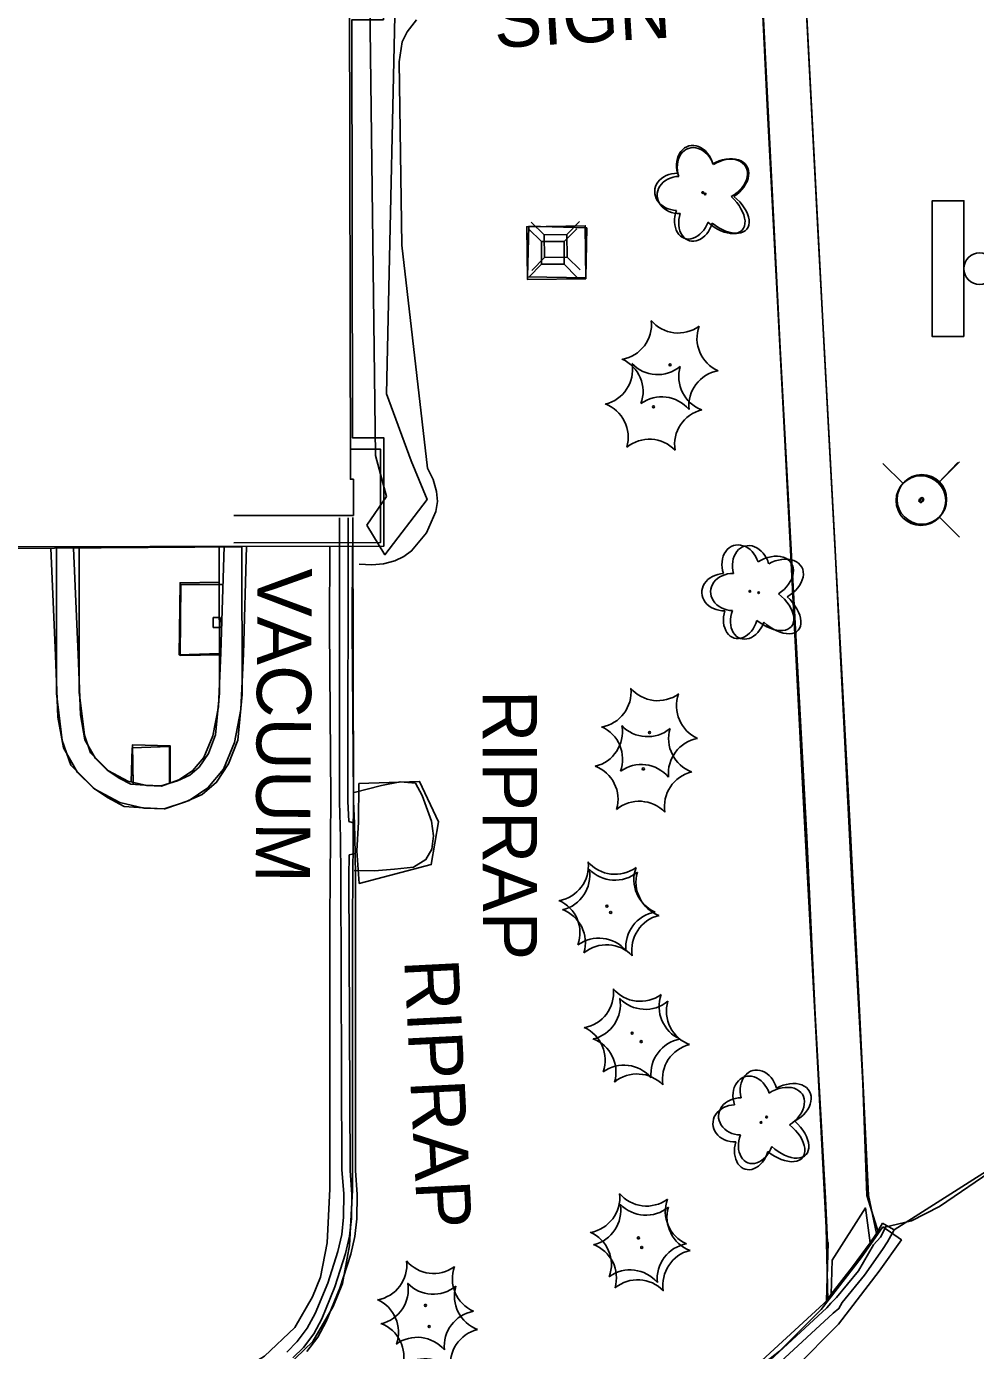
# Model space of a CAD drawing. Extents: x 588843 to 2552415, y 180129 to 269402.
# Drawn here: x 594584.3 to 594689.3, y 184634.7 to 184781.1 of the extents above; entities that cross this region are included whole.
import ezdxf

# ---------------------------------------------------------------- set-up
doc = ezdxf.new("R2010")
doc.units = 0
for name, color, linetype in [('Default', 7, 'Continuous'), ('E_AREA', 7, 'Continuous'), ('E_BLD', 7, 'Continuous'), ('E_BLD_HvyDash', 7, 'Continuous'), ('E_BLD_Text', 7, 'Continuous'), ('E_BLD_Vacuum', 7, 'Continuous'), ('E_DRN_RipRap', 7, 'Continuous'), ('E_DRN_RipRap_Text', 7, 'Continuous'), ('E_DWY', 7, 'Continuous'), ('E_LAND_ShrubLine', 7, 'Continuous'), ('E_LAND_Vegetation', 7, 'Continuous'), ('E_MISCPROP_Planter', 7, 'Continuous'), ('E_PATH_Sidewalk', 7, 'Continuous'), ('E_RDWY_AsphConc', 7, 'Continuous'), ('E_RDWY_C_and_G', 7, 'Continuous'), ('E_SGN', 7, 'Continuous'), ('E_SGN_Text', 7, 'Continuous'), ('E_UTL_AG_Bold', 7, 'Continuous'), ('E_UTL_WHydrant', 7, 'Continuous')]:
    doc.layers.add(name, color=color, linetype=linetype)

# ---------------------------------------------------------------- blocks, each defined once
blk = doc.blocks.new('HYD')
at = {"layer": 'Default'}
for p, q in [((-3.84, 3.84), (-8.32, 8.32)), ((3.84, 3.84), (8.32, 8.32))]:
    blk.add_line(p, q, dxfattribs=at)
for radius in [5.48, 0.42]:
    blk.add_circle((0, 0), radius, dxfattribs=at)
blk = doc.blocks.new('RIPRT')
at = {"layer": 'E_DRN_RipRap_Text'}
blk.add_text('RIPRAP', height=12, dxfattribs=at).set_placement((-0.14, -3.59))
blk = doc.blocks.new('PED')
at = {"layer": 'Default'}
for p, q in [((-2.5, 2.5), (-5.33, 5.33)), ((2.5, 2.5), (5.33, 5.33)), ((-2.5, -2.5), (-5.33, -5.33)), ((2.5, -2.5), (5.33, -5.33))]:
    blk.add_line(p, q, dxfattribs=at)
blk.add_lwpolyline([(-2.5, -2.5), (2.5, -2.5), (2.5, 2.5), (-2.5, 2.5)], close=True, dxfattribs=at)
blk = doc.blocks.new('VACO')
at = {"layer": 'E_BLD_Vacuum'}
blk.add_lwpolyline([(0, 1.5), (0, 0), (2.2, 0), (2.2, 1.5), (0, 1.5)], close=True, dxfattribs=at)
blk = doc.blocks.new('VAC')
at = {"layer": 'E_BLD_Text'}
blk.add_text('VACUUM', height=12, dxfattribs=at).set_placement((-33.33, -6))
blk = doc.blocks.new('CTRE_1_1')
at = {"layer": 'Default'}
blk.add_circle((0, 0), 0.223, dxfattribs=at)
for centre, start, end in [((-11.97, 8.96), 280.2067, 5.9716), ((1.81, 14.92), 220.2113, 305.9762), ((13.83, 5.89), 160.2113, 245.9762), ((-13.83, -5.9), 340.2113, 65.9762), ((12.03, -9.04), 100.2511, 185.9272), ((-1.81, -14.93), 40.2113, 125.9762)]:
    blk.add_arc(centre, 7.87, start, end, dxfattribs=at)
blk = doc.blocks.new('DTRE_1_1')
at = {"layer": 'Default'}
blk.add_circle((-0.18, 0), 0.183, dxfattribs=at)
for centre, major_axis, ratio in [((-1.87, 5.32), (1.36, -4.98), 0.782863), ((4.06, 2.74), (-5.27, -2.93), 0.691916), ((-5.87, 0.15), (4.93, -0.12), 0.832022), ((3.54, -3.71), (-5.01, 4.58), 0.560249), ((-2.49, -5.24), (1.8, 4.86), 0.716896)]:
    blk.add_ellipse(centre, major_axis=major_axis, ratio=ratio, start_param=1.570796, end_param=4.712389, dxfattribs=at)
blk = doc.blocks.new('SGN_1')
at = {"layer": 'Default'}
blk.add_lwpolyline([(-3.5, -15), (-10.5, -15), (-10.5, 15), (-3.5, 15)], close=True, dxfattribs=at)
blk.add_circle((0, 0), 3.5, dxfattribs=at)
blk = doc.blocks.new('PED_3')
at = {"layer": 'E_UTL_AG_Bold'}
for p, q in [((-8.2, 8.2), (-17.48, 17.48)), ((8.2, 8.2), (17.48, 17.48)), ((-8.2, -8.2), (-17.48, -17.48)), ((8.2, -8.2), (17.48, -17.48))]:
    blk.add_line(p, q, dxfattribs=at)
blk.add_lwpolyline([(-8.2, -8.2), (8.2, -8.2), (8.2, 8.2), (-8.2, 8.2)], close=True, dxfattribs=at)
blk = doc.blocks.new('HYD_3')
at = {"layer": 'E_UTL_WHydrant'}
for p, q in [((-12.59, 12.59), (-27.29, 27.29)), ((12.6, 12.59), (27.29, 27.29))]:
    blk.add_line(p, q, dxfattribs=at)
for radius in [18, 1.38]:
    blk.add_circle((0, 0), radius, dxfattribs=at)
blk = doc.blocks.new('RIPRT_3')
at = {"layer": 'E_DRN_RipRap_Text'}
blk.add_text('RIPRAP', height=39.37, dxfattribs=at).set_placement((-0.46, -11.78))
blk = doc.blocks.new('DTRE_4')
at = {"layer": 'E_LAND_Vegetation'}
blk.add_circle((-0.6, 0), 0.601, dxfattribs=at)
for centre, major_axis, ratio in [((-6.14, 17.45), (4.46, -16.34), 0.782863), ((13.31, 8.98), (-17.3, -9.61), 0.691916), ((-19.26, 0.5), (16.18, -0.4), 0.832022), ((11.62, -12.16), (-16.44, 15.03), 0.560249), ((-8.18, -17.2), (5.91, 15.93), 0.716896)]:
    blk.add_ellipse(centre, major_axis=major_axis, ratio=ratio, start_param=1.570796, end_param=4.712389, dxfattribs=at)
blk = doc.blocks.new('CTRE_4')
at = {"layer": 'E_LAND_Vegetation'}
blk.add_circle((0, 0), 0.733, dxfattribs=at)
for centre, radius, start, end in [((-39.28, 29.41), 25.81, 280.2067, 5.97162), ((5.93, 48.96), 25.81, 220.21132, 305.97623), ((45.37, 19.34), 25.81, 160.21133, 245.97624), ((-45.37, -19.35), 25.81, 340.21132, 65.97623), ((39.47, -29.65), 25.83, 100.25111, 185.92721), ((-5.93, -48.97), 25.81, 40.21133, 125.97624)]:
    blk.add_arc(centre, radius, start, end, dxfattribs=at)
blk = doc.blocks.new('SIGN_3')
at = {"layer": 'E_SGN'}
blk.add_text('SIGN', height=39.37, dxfattribs=at).set_placement((-56.13, -19.68))

msp = doc.modelspace()

# ---------------------------------------------------------------- linework, layer by layer
at = {"layer": 'E_AREA'}
msp.add_lwpolyline([(594646.19, 184753.21), (594639.73, 184753.12), (594639.65, 184758.97), (594646.11, 184759.07)], close=True, dxfattribs=at)
for points in [[(594605.67, 184711.8), (594601.23, 184711.63), (594601.33, 184719.62), (594605.65, 184719.67)], [(594596.13, 184697.33), (594596.06, 184701.69), (594600.24, 184701.58), (594600.24, 184697.47)]]:
    msp.add_lwpolyline(points, dxfattribs=at)
at = {"layer": 'E_BLD'}
for points in [[(594608.14, 184723.58), (594571.85, 184723.33), (594571.78, 184734.03), (594574.21, 184734.05), (594573.89, 184781.74), (594571.61, 184781.72), (594571.54, 184792.23), (594601.99, 184792.44)], [(594597.01, 184789.06), (594620.38, 184789.1), (594620.39, 184785.1), (594620.06, 184785.1), (594620.15, 184731.06), (594620.48, 184731.06), (594620.49, 184727.06), (594607.25, 184727.04)], [(594620.15, 184734.36), (594623.48, 184734.37), (594623.49, 184724.07), (594607.25, 184724.04)]]:
    msp.add_lwpolyline(points, dxfattribs=at)
msp.add_lwpolyline([(594571.85, 184792.25), (594623.79, 184792.33), (594623.8, 184781.84), (594620.3, 184781.83), (594620.37, 184735.63), (594623.84, 184735.63), (594623.86, 184723.66), (594572.06, 184723.57), (594572.05, 184734.14), (594575.19, 184734.15), (594575.11, 184783.48), (594571.86, 184783.48)], close=True, dxfattribs=at)
at = {"layer": 'E_BLD_HvyDash'}
msp.add_lwpolyline([(594673.3, 184640.99), (594673.42, 184644.74), (594677.08, 184650.51), (594677.62, 184646.65)], dxfattribs=at)
at = {"layer": 'E_DRN_RipRap'}
for points in [[(594621.1, 184697.43), (594627.8, 184697.66), (594629.89, 184693.2), (594629.09, 184688.46), (594621.12, 184686.37), (594620.87, 184689.99), (594621.04, 184693.16)], [(594620.58, 184696.41), (594623.57, 184697.19), (594625.64, 184697.62), (594627.33, 184697.45), (594628.07, 184696.11), (594629.1, 184693.26), (594629.35, 184691.65), (594629.14, 184690.17), (594628.5, 184689.02), (594627.14, 184688.19), (594625.03, 184687.97), (594622.82, 184687.78), (594620.58, 184687.81)], [(594621.1, 184697.43), (594621.04, 184693.16)]]:
    msp.add_lwpolyline(points, dxfattribs=at)
at = {"layer": 'E_DWY'}
for points in [[(594587.02, 184723.43), (594587.56, 184711.58), (594587.81, 184704.74), (594588.42, 184701.38), (594589.97, 184698.64), (594591.71, 184696.94), (594593.31, 184695.88), (594595.16, 184694.89), (594597.29, 184694.74), (594599.58, 184694.64), (594601.93, 184695.39), (594603.75, 184696.2), (594605.35, 184697.56), (594606.68, 184699.6), (594607.71, 184702.2), (594608.19, 184707.27), (594608.14, 184723.58)], [(594587.67, 184723.6), (594587.66, 184707.38), (594588.29, 184702.18), (594589.24, 184699.46), (594591.89, 184696.78), (594594.65, 184695.33), (594597.31, 184694.7), (594599.65, 184694.62), (594602.32, 184695.56), (594604.4, 184696.93), (594606.12, 184698.99), (594607.35, 184701.96), (594608.05, 184705.59), (594608.33, 184711.75), (594608.68, 184723.63)], [(594589.53, 184723.45), (594590.06, 184711.68), (594590.3, 184705.01), (594590.8, 184702.24), (594591.97, 184700.18), (594593.28, 184698.9), (594594.59, 184698.03), (594595.87, 184697.35), (594597.43, 184697.24), (594599.25, 184697.16), (594601.03, 184697.72), (594602.4, 184698.34), (594603.45, 184699.23), (594604.45, 184700.75), (594605.25, 184702.79), (594605.69, 184707.39), (594605.64, 184723.56)], [(594590.17, 184723.6), (594590.16, 184707.53), (594590.74, 184702.75), (594591.41, 184700.82), (594593.4, 184698.82), (594595.53, 184697.69), (594597.64, 184697.19), (594599.27, 184697.14), (594601.2, 184697.81), (594602.71, 184698.81), (594603.96, 184700.3), (594604.95, 184702.68), (594605.56, 184705.88), (594605.83, 184711.85), (594606.18, 184723.63)], [(594617.87, 184652.26), (594617.87, 184682.51), (594617.98, 184695.78), (594617.85, 184714.65), (594617.87, 184723.65)], [(594620.37, 184652.26), (594620.37, 184682.5), (594620.48, 184695.78), (594620.35, 184714.65), (594620.37, 184723.65)], [(594698.83, 184659.48), (594691.63, 184655), (594685.27, 184650.67), (594682.16, 184649.1), (594679.09, 184648.35)], [(594554.3, 184628.4), (594573.37, 184627.04), (594585.2, 184627.24), (594601.3, 184628.05), (594604.86, 184628.68), (594608.73, 184630.03), (594612.19, 184632.11), (594615.99, 184635.73), (594618.23, 184639.6), (594619.27, 184642.16), (594620.05, 184646.34), (594620.38, 184652.49)], [(594554.48, 184630.89), (594573.44, 184629.54), (594585.12, 184629.74), (594601.03, 184630.54), (594604.23, 184631.1), (594607.66, 184632.3), (594610.67, 184634.11), (594614.01, 184637.29), (594615.97, 184640.7), (594616.86, 184642.87), (594617.57, 184646.64), (594617.88, 184652.63)], [(594679.01, 184648.41), (594676.6, 184645.01), (594672.2, 184639.3), (594667.6, 184634.68), (594662.06, 184630.33), (594656.62, 184627.07), (594652.4, 184625.21), (594646.92, 184622.88), (594643.5, 184622.02), (594637.03, 184621.21)], [(594679.01, 184648.41), (594681.05, 184646.97), (594678.61, 184643.52), (594674.09, 184637.65), (594669.27, 184632.81), (594663.48, 184628.26), (594657.77, 184624.85), (594653.4, 184622.91), (594647.72, 184620.51), (594643.97, 184619.56), (594637.34, 184618.73)]]:
    msp.add_lwpolyline(points, dxfattribs=at)
at = {"layer": 'E_LAND_ShrubLine'}
for points in [[(594622.17, 184792.64), (594625.27, 184792.33), (594624.15, 184740.49), (594626.86, 184733.08), (594628.62, 184728.8), (594623.96, 184722.7), (594621.98, 184725.96)], [(594622.17, 184792.64), (594622.92, 184733.69), (594624.14, 184729.13), (594621.98, 184725.96)]]:
    msp.add_lwpolyline(points, dxfattribs=at)
at = {"layer": 'E_MISCPROP_Planter'}
msp.add_lwpolyline([(594627.46, 184781.83), (594626.43, 184780.52), (594626.43, 184780.52), (594625.89, 184779.4), (594625.89, 184779.4), (594625.53, 184777.18), (594625.53, 184777.18), (594625.83, 184756.91), (594628.68, 184732.26), (594629.29, 184731.02), (594629.67, 184729.69), (594629.67, 184729.69), (594629.76, 184728.58), (594629.59, 184727.49), (594629.59, 184727.49), (594628.57, 184725.14), (594628.57, 184725.14), (594626.91, 184723.15), (594626.91, 184723.15), (594626.04, 184722.51), (594625.07, 184722.05), (594625.07, 184722.05), (594623.82, 184721.71), (594622.53, 184721.58), (594622.53, 184721.58), (594621.11, 184721.68)], dxfattribs=at)
at = {"layer": 'E_PATH_Sidewalk'}
for points in [[(594669.6, 184841.07), (594668.31, 184833.93), (594668.28, 184832.41), (594669.05, 184813.25), (594670.72, 184811.95), (594673.71, 184809.15), (594675.9, 184805.35), (594677.5, 184799.87), (594677.72, 184794.89), (594677.23, 184792.47), (594675.59, 184789.26), (594673.55, 184786.77), (594671.36, 184784.84), (594670.49, 184783.96), (594671.86, 184757.97), (594673.7, 184723.96), (594675.62, 184685.94), (594676.8, 184664.3), (594677.24, 184651.89), (594678.54, 184647.75)], [(594672.94, 184640.26), (594672.75, 184648.36), (594671.86, 184665.3), (594670.32, 184693.9), (594668.16, 184735.38), (594666.26, 184771.65), (594665.57, 184786.08), (594670.81, 184791.14), (594672.55, 184794.02), (594672.81, 184796.71), (594672.11, 184801.41), (594670.94, 184804.1), (594668.6, 184807.03), (594665.88, 184809.34), (594664.37, 184810.49), (594663.32, 184831.88), (594660.05, 184831.9), (594659.4, 184836.03)], [(594672.76, 184640.23), (594672.95, 184646.7), (594672.9, 184646.72), (594672.67, 184651.6), (594671.54, 184671.85), (594670.6, 184691.48), (594667.67, 184745.54), (594665.59, 184786.32)], [(594678.3, 184647.67), (594677.43, 184651.88), (594676.42, 184672.34), (594675.42, 184691.86), (594672.55, 184744.93), (594670.49, 184784.28)], [(594606.06, 184719.41), (594601.39, 184719.42), (594601.34, 184711.56), (594605.82, 184711.64)], [(594600.14, 184697.44), (594600.15, 184701.5), (594596.01, 184701.36), (594595.91, 184697.6)]]:
    msp.add_lwpolyline(points, dxfattribs=at)
at = {"layer": 'E_RDWY_AsphConc'}
msp.add_lwpolyline([(594639.88, 184759.03), (594639.72, 184753.44), (594646.18, 184753.3), (594646.28, 184758.83)], close=True, dxfattribs=at)
msp.add_lwpolyline([(594680.24, 184648.09), (594698.74, 184659.86)], dxfattribs=at)
at = {"layer": 'E_RDWY_C_and_G'}
for points in [[(594618.95, 184726.8), (594618.96, 184695.38), (594619.04, 184691.41), (594619.1, 184686.98), (594619.2, 184654.72), (594619.41, 184652.11), (594619.4, 184649.49), (594619.4, 184649.49), (594619.19, 184647.57), (594618.77, 184645.68), (594618.77, 184645.68), (594617.64, 184642.21), (594616.26, 184638.83), (594616.26, 184638.83), (594615.38, 184637.21), (594614.28, 184635.73), (594614.28, 184635.73), (594613.12, 184634.56)], [(594620.42, 184726.82), (594620.48, 184695.44), (594620.61, 184693.04), (594620.63, 184691.36), (594620.66, 184689.68), (594620.7, 184687.04), (594620.73, 184654.66), (594620.91, 184651.98), (594620.86, 184649.3), (594620.86, 184649.3), (594620.64, 184647.34), (594620.21, 184645.41), (594620.21, 184645.41), (594618.99, 184641.64), (594617.48, 184637.96), (594617.48, 184637.96), (594616.54, 184636.23), (594615.34, 184634.65)], [(594619.91, 184726.79), (594619.88, 184695.46), (594619.98, 184693.23), (594620.61, 184693.04)], [(594620.66, 184689.68), (594620.02, 184689.53), (594619.98, 184687.12), (594620.13, 184654.65), (594620.31, 184652), (594620.27, 184649.35), (594620.27, 184649.35), (594620.05, 184647.39), (594619.62, 184645.46), (594619.62, 184645.46), (594618.44, 184641.8), (594616.99, 184638.24), (594616.99, 184638.24), (594616.1, 184636.59), (594614.97, 184635.09), (594614.97, 184635.09), (594613.8, 184633.93)], [(594627.93, 184620.38), (594642.38, 184622.21), (594646.24, 184623.13), (594646.24, 184623.13), (594649.73, 184624.28), (594649.73, 184624.28), (594652.52, 184625.46), (594663.8, 184631.94), (594672.48, 184639.95), (594672.76, 184640.23), (594673.3, 184640.99), (594675.67, 184643.99), (594677.62, 184646.65), (594678.3, 184647.67), (594678.95, 184648.83)], [(594628.07, 184619.86), (594642.43, 184621.64), (594646.35, 184622.42), (594646.35, 184622.42), (594649.9, 184623.82), (594649.9, 184623.82), (594651.31, 184624.41), (594652.74, 184624.98), (594664.15, 184631.48), (594672.8, 184639.45), (594673.27, 184640), (594673.87, 184640.61), (594676.31, 184643.55), (594677.97, 184646.43), (594678.73, 184647.29), (594679.41, 184648.56)], [(594628.14, 184618.94), (594642.49, 184620.72), (594646.72, 184621.65), (594646.72, 184621.65), (594650.51, 184622.53), (594650.51, 184622.53), (594653.34, 184623.69), (594664.79, 184630.8), (594673.52, 184638.86), (594674.15, 184639.39), (594674.52, 184640.04), (594676.96, 184643.06), (594678.97, 184645.93), (594679.51, 184646.77), (594680.24, 184648.09), (594679.41, 184648.56), (594678.95, 184648.83)]]:
    msp.add_lwpolyline(points, dxfattribs=at)

# ---------------------------------------------------------------- block references
at = {"layer": 'E_BLD_Text', "xscale": 0.5000000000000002, "yscale": 0.5000000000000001, "rotation": -90.36283032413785}
msp.add_blockref('VAC', (594612.79, 184704.55), dxfattribs=at)
at = {"layer": 'E_BLD_Vacuum', "xscale": 0.5000000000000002, "yscale": 0.5000000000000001, "rotation": -90.36283032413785}
msp.add_blockref('VACO', (594604.99, 184715.77), dxfattribs=at)
at = {"layer": 'E_DRN_RipRap_Text'}
for name, p, xscale, yscale, rotation in [('RIPRT', (594636.58, 184707.7), 0.5, 0.5, -89.98949477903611), ('RIPRT_3', (594627.89, 184677.94), 0.15240030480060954, 0.15240030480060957, -87.10404271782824)]:
    msp.add_blockref(name, p, dxfattribs=dict(at, xscale=xscale, yscale=yscale, rotation=rotation))
at = {"layer": 'E_LAND_Vegetation', "xscale": 0.15240030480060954, "yscale": 0.15240030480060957, "rotation": 3.4338469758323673}
for name, p in [('DTRE_4', (594659.46, 184762.58)), ('CTRE_4', (594653.65, 184739.05)), ('DTRE_4', (594664.4, 184718.67)), ('CTRE_4', (594652.53, 184699.03)), ('CTRE_4', (594648.92, 184683.17)), ('CTRE_4', (594652.3, 184668.89)), ('DTRE_4', (594665.62, 184659.96)), ('CTRE_4', (594652.35, 184646.14)), ('CTRE_4', (594628.86, 184637.4))]:
    msp.add_blockref(name, p, dxfattribs=at)
at = {"layer": 'E_LAND_Vegetation', "xscale": 0.5, "yscale": 0.5}
for name, p in [('DTRE_1_1', (594659.19, 184762.74)), ('CTRE_1_1', (594655.48, 184743.69)), ('DTRE_1_1', (594665.37, 184718.51)), ('CTRE_1_1', (594653.22, 184703.05)), ('CTRE_1_1', (594648.51, 184683.86)), ('CTRE_1_1', (594651.29, 184669.82)), ('DTRE_1_1', (594666.24, 184660.55)), ('CTRE_1_1', (594651.98, 184647.19)), ('CTRE_1_1', (594628.44, 184639.74))]:
    msp.add_blockref(name, p, dxfattribs=at)
at = {"layer": 'E_SGN', "xscale": 0.5, "yscale": 0.5}
msp.add_blockref('SGN_1', (594689.71, 184754.33), dxfattribs=at)
at = {"layer": 'E_SGN_Text', "xscale": 0.15240030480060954, "yscale": 0.15240030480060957, "rotation": 3.4338469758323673}
msp.add_blockref('SIGN_3', (594644.5, 184782.22), dxfattribs=at)
at = {"layer": 'E_UTL_AG_Bold'}
for name, p, xscale, yscale, rotation in [('PED_3', (594642.83, 184756.84), 0.15240030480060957, 0.15240030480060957, 0.8014450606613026), ('PED', (594642.52, 184756.07), 0.5, 0.5, -89.98949477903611)]:
    msp.add_blockref(name, p, dxfattribs=dict(at, xscale=xscale, yscale=yscale, rotation=rotation))
at = {"layer": 'E_UTL_WHydrant'}
for name, p, xscale, yscale, rotation in [('HYD_3', (594683.21, 184728.69), 0.15240030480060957, 0.15240030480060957, 0.8014450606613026), ('HYD', (594683.32, 184728.82), 0.5, 0.5, -89.98949477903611)]:
    msp.add_blockref(name, p, dxfattribs=dict(at, xscale=xscale, yscale=yscale, rotation=rotation))

doc.saveas('drawing.dxf')
